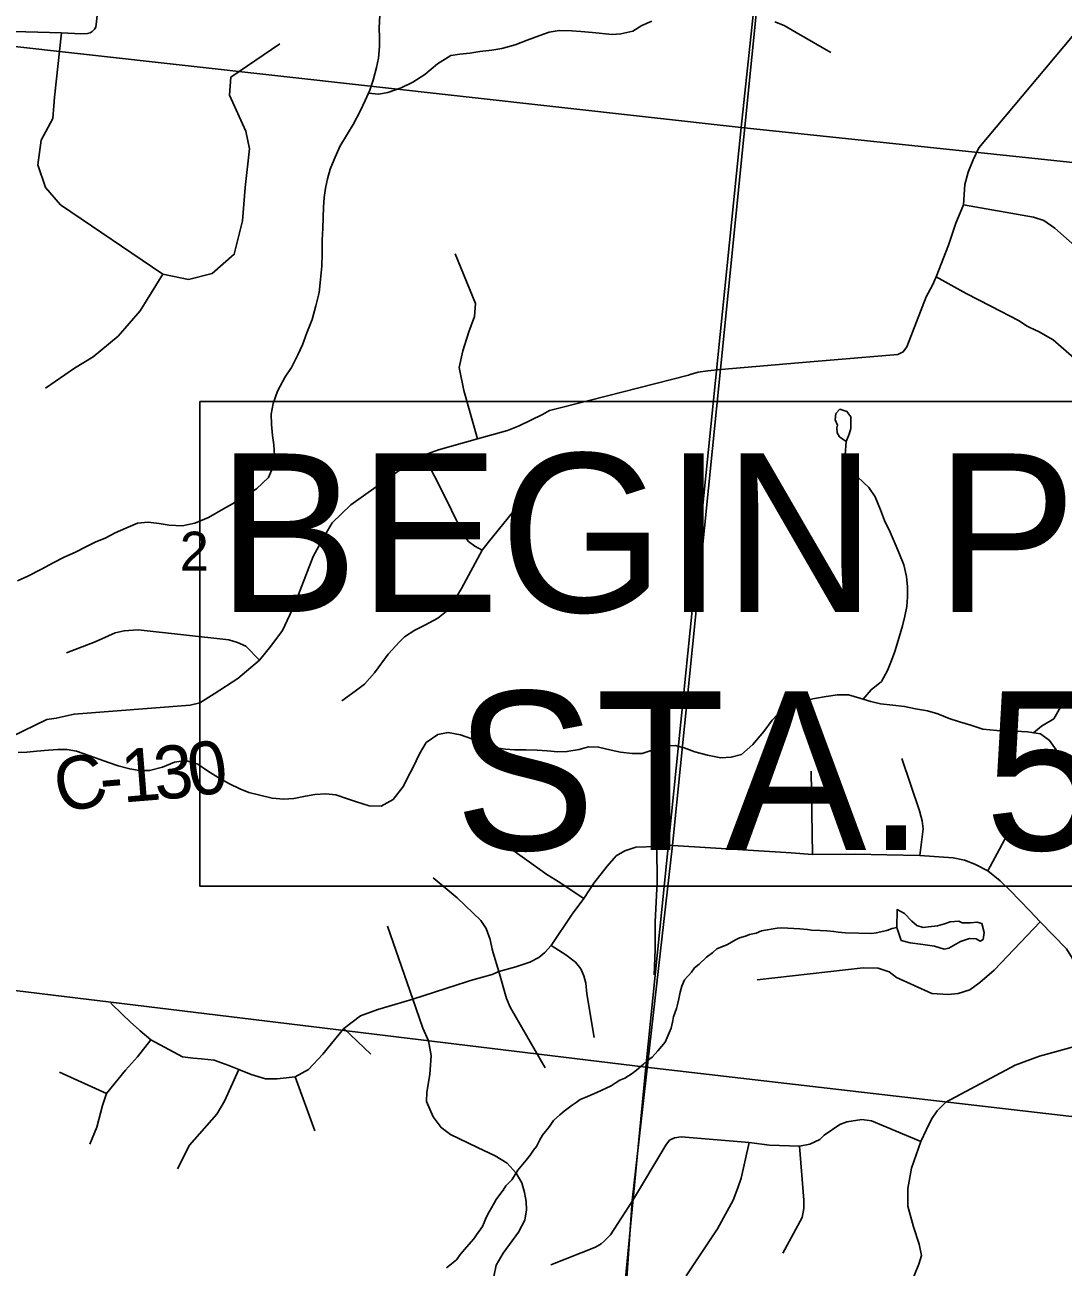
# Model space of a CAD drawing. Extents: x 0 to 43.4, y -8.1 to 22.
# Drawn here: x 3.172 to 4.286, y 18.481 to 19.813 of the extents above; entities that cross this region are included whole.
import ezdxf

# ---------------------------------------------------------------- set-up
doc = ezdxf.new("R2010")
doc.units = 0
for name, color, linetype in [('GM_X_Corporation', 7, 'Continuous'), ('GM_X_County_Road', 7, 'Continuous'), ('GM_X_County_Road_Text', 7, 'Continuous'), ('GM_X_Minor_Lake', 7, 'Continuous'), ('GM_X_Minor_River', 7, 'Continuous'), ('GM_X_Section_Text', 7, 'Continuous'), ('GM_X_Township_Road', 7, 'Continuous'), ('SH_Masking', 7, 'Continuous'), ('SH_Text', 7, 'Continuous')]:
    doc.layers.add(name, color=color, linetype=linetype)

msp = doc.modelspace()

# ---------------------------------------------------------------- linework, layer by layer
at = {"layer": 'GM_X_Corporation'}
for points in [[(8.9, 20.9), (4.0645, 20.9), (4.0111, 20.3696), (4.0006, 20.2658), (3.9936, 20.1953), (3.918, 19.4441), (3.8667, 18.9338), (3.8234, 18.5529), (3.8126, 18.3973), (3.8023, 18.3182), (3.7454, 17.7286), (3.744, 17.7149), (3.7921, 17.7096), (3.9407, 17.6938), (4.0716, 17.683), (4.1644, 17.6753), (4.3821, 17.6581)], [(3.8126, 18.3973), (3.8234, 18.5529), (3.8667, 18.9338), (3.918, 19.4441), (3.9936, 20.1953)]]:
    msp.add_lwpolyline(points, dxfattribs=at)
for points in [[(4.0476, 20.7082), (3.9403, 19.703), (2.9428, 19.8144), (3.042, 20.8098)], [(4.0476, 20.7082), (5.0456, 20.604), (4.9462, 19.5972), (3.9403, 19.703)], [(2.9428, 19.8144), (3.9403, 19.703), (3.8378, 18.6959), (2.8429, 18.8166)], [(3.9403, 19.703), (4.9462, 19.5972), (4.8473, 18.579), (3.8378, 18.6959)], [(3.8378, 18.6959), (3.7435, 17.7155), (2.8521, 17.7909), (2.8154, 17.7918), (2.8147, 17.7929), (2.7902, 17.8357), (2.7645, 17.8808), (2.7638, 17.882), (2.7489, 17.9091), (2.8429, 18.8166)], [(4.8473, 18.579), (4.7377, 17.6242), (3.7435, 17.7155), (3.8378, 18.6959)]]:
    msp.add_lwpolyline(points, close=True, dxfattribs=at)
at = {"layer": 'GM_X_County_Road'}
for points in [[(2.8955, 19.8202), (2.9503, 19.8114), (3.0205, 19.8099), (3.2114, 19.8047), (3.2321, 19.8036), (3.239, 19.8038), (3.2419, 19.8047), (3.244, 19.8059), (3.2466, 19.8085), (3.2479, 19.8108), (3.2621, 19.9316)], [(4.0143, 19.4518), (4.0184, 19.4522), (4.1083, 19.4599), (4.1141, 19.4627), (4.118, 19.468), (4.1385, 19.5218), (4.1456, 19.5341), (4.1492, 19.543), (4.1627, 19.577), (4.1706, 19.6007), (4.1786, 19.6202), (4.1801, 19.6419), (4.1838, 19.6551), (4.1891, 19.6686), (4.1952, 19.6814), (4.3047, 19.812)], [(3.8856, 19.4382), (3.8941, 19.4408), (3.9044, 19.4424), (3.9183, 19.4436), (4.0143, 19.4518)], [(3.1185, 19.0315), (3.1954, 19.0686), (3.2057, 19.0698), (3.2248, 19.0743), (3.3492, 19.0839), (3.3595, 19.0863), (3.375, 19.0962), (3.4005, 19.1126), (3.4235, 19.1322), (3.4356, 19.147), (3.4482, 19.1638), (3.4611, 19.1915), (3.4811, 19.2431), (3.4915, 19.2622), (3.5014, 19.2794), (3.5217, 19.2986), (3.5871, 19.3451), (3.5998, 19.352), (3.6155, 19.3577), (3.6575, 19.3695), (3.6897, 19.3785), (3.702, 19.3835), (3.727, 19.3954), (3.7347, 19.3998), (3.7772, 19.4106), (3.8838, 19.4376), (3.8856, 19.4382)], [(4.0436, 18.2811), (4.0476, 18.2871), (4.0548, 18.2983), (4.0665, 18.3252), (4.0876, 18.3787), (4.1308, 18.4847), (4.1337, 18.4941), (4.1313, 18.506), (4.125, 18.5247), (4.1188, 18.5469), (4.1189, 18.5659), (4.1229, 18.5875), (4.133, 18.6161), (4.1389, 18.6289), (4.1445, 18.6401), (4.1504, 18.6491), (4.1598, 18.6583), (4.2341, 18.6979), (4.2601, 18.7077), (4.3134, 18.7223)]]:
    msp.add_lwpolyline(points, dxfattribs=at)
at = {"layer": 'GM_X_Minor_Lake'}
for points in [[(4.0527, 19.3666), (4.056, 19.3743), (4.0577, 19.3804), (4.058, 19.3929), (4.0536, 19.3987), (4.0461, 19.4012), (4.0418, 19.3964), (4.0412, 19.3899), (4.0434, 19.3842)], [(4.0434, 19.3842), (4.0429, 19.3812), (4.0432, 19.3758), (4.0457, 19.3716), (4.0528, 19.3667)], [(4.112, 18.8316), (4.1214, 18.8291), (4.1327, 18.8277), (4.1475, 18.8254), (4.1581, 18.8225), (4.163, 18.8235), (4.1754, 18.8307), (4.185, 18.8339), (4.1922, 18.8333), (4.1967, 18.8309), (4.1997, 18.8328), (4.2007, 18.8403), (4.1983, 18.8499), (4.193, 18.8512), (4.1862, 18.8506), (4.1774, 18.8505), (4.1737, 18.8525), (4.1645, 18.8516), (4.1584, 18.8494), (4.1507, 18.8474), (4.1412, 18.8461), (4.1355, 18.8455), (4.1287, 18.8476), (4.1231, 18.8523), (4.1154, 18.8604), (4.1075, 18.8648), (4.1073, 18.8454)], [(4.1073, 18.8454), (4.1075, 18.8648), (4.1154, 18.8604), (4.1231, 18.8523), (4.1287, 18.8476), (4.1355, 18.8455), (4.1412, 18.8461), (4.1507, 18.8474), (4.1584, 18.8494), (4.1645, 18.8516), (4.1737, 18.8525), (4.1774, 18.8505), (4.1862, 18.8506), (4.193, 18.8512), (4.1983, 18.8499), (4.2007, 18.8403), (4.1997, 18.8328), (4.1967, 18.8309), (4.1922, 18.8333), (4.185, 18.8339), (4.1754, 18.8307), (4.163, 18.8235), (4.1581, 18.8225), (4.1475, 18.8254), (4.1327, 18.8277), (4.1214, 18.8291), (4.1119, 18.8317)], [(4.1073, 18.8454), (4.112, 18.8316)]]:
    msp.add_lwpolyline(points, dxfattribs=at)
at = {"layer": 'GM_X_Minor_River'}
for points in [[(3.3043, 19.28), (3.3161, 19.2785), (3.3267, 19.277), (3.3407, 19.2763), (3.3544, 19.2789), (3.369, 19.285), (3.3849, 19.2944), (3.3945, 19.2998), (3.4081, 19.3082), (3.4204, 19.3158), (3.4333, 19.328), (3.4374, 19.3378), (3.4397, 19.3514), (3.4389, 19.3628), (3.4377, 19.3731), (3.4365, 19.3846), (3.4361, 19.396), (3.4383, 19.4073), (3.4428, 19.4205), (3.4513, 19.4358), (3.458, 19.4459), (3.4649, 19.4594), (3.4697, 19.4703), (3.4743, 19.4831), (3.48, 19.4974), (3.4842, 19.5121), (3.4877, 19.5264), (3.4892, 19.5401), (3.4904, 19.5545), (3.4908, 19.5682), (3.4908, 19.5822), (3.4916, 19.5951), (3.4922, 19.6179), (3.4929, 19.6282), (3.4943, 19.638), (3.4965, 19.6482), (3.4995, 19.6584), (3.5036, 19.6689), (3.5097, 19.6828), (3.518, 19.6963), (3.524, 19.7064), (3.5316, 19.7206), (3.5369, 19.7322), (3.5418, 19.7431), (3.5455, 19.754), (3.549, 19.7676), (3.5511, 19.7774), (3.5523, 19.7899), (3.5522, 19.7998), (3.5521, 19.8101), (3.5525, 19.8234)], [(3.5403, 19.7399), (3.5515, 19.739), (3.5611, 19.7407), (3.5757, 19.7456), (3.588, 19.7517), (3.6011, 19.76), (3.6144, 19.7715), (3.6287, 19.7802), (3.6386, 19.7818), (3.6493, 19.783), (3.66, 19.7846), (3.6729, 19.7861), (3.6836, 19.7877), (3.6978, 19.7919), (3.7108, 19.7968), (3.7243, 19.8018), (3.7342, 19.8053), (3.7449, 19.8073), (3.7586, 19.8069), (3.7684, 19.8062), (3.7806, 19.8051), (3.8018, 19.803), (3.8113, 19.8035), (3.8239, 19.8065), (3.8336, 19.8124), (3.8443, 19.817)], [(3.9765, 19.8166), (3.9862, 19.8126), (3.9993, 19.805), (4.0363, 19.7834)], [(4.0712, 19.0903), (4.0796, 19.1005), (4.0909, 19.1093), (4.0973, 19.1209), (4.1014, 19.1318), (4.1051, 19.1416), (4.1097, 19.1567), (4.1131, 19.1691), (4.1157, 19.1793), (4.1179, 19.1895), (4.1185, 19.1998), (4.1185, 19.2108), (4.1177, 19.2218), (4.1146, 19.2345), (4.1093, 19.2475), (4.1043, 19.2595), (4.1001, 19.2695), (4.094, 19.2818), (4.0897, 19.2933), (4.0841, 19.3072), (4.0771, 19.3173), (4.0653, 19.3283), (4.0555, 19.3426), (4.0519, 19.3522), (4.0527, 19.3666)], [(3.1639, 19.2171), (3.1751, 19.2221), (3.1897, 19.2296), (3.2024, 19.2365), (3.214, 19.2426), (3.2263, 19.248), (3.2379, 19.2541), (3.2475, 19.2588), (3.2587, 19.2634), (3.2687, 19.2688), (3.2802, 19.2738), (3.2929, 19.2791), (3.3043, 19.28)], [(3.1647, 19.033), (3.1742, 19.0335), (3.1848, 19.0347), (3.1974, 19.0355), (3.2073, 19.0364), (3.2172, 19.0365), (3.2274, 19.0346), (3.2405, 19.0301), (3.2518, 19.026), (3.2616, 19.0226), (3.2721, 19.0189), (3.2845, 19.0155), (3.2944, 19.0137), (3.3058, 19.0138), (3.3195, 19.0176), (3.3326, 19.0229), (3.3444, 19.0245), (3.3576, 19.0207), (3.3677, 19.0135), (3.3792, 19.0064), (3.3916, 18.9996), (3.4024, 18.9943), (3.4122, 18.9902), (3.4227, 18.9876), (3.4371, 18.9842), (3.4496, 18.9831), (3.4606, 18.9839), (3.4728, 18.9862), (3.4831, 18.9882), (3.4949, 18.989), (3.5055, 18.9879), (3.5179, 18.9834), (3.5277, 18.9801), (3.5413, 18.9759), (3.5542, 18.9755), (3.5669, 18.9828), (3.578, 18.9969), (3.5828, 19.0067), (3.588, 19.0168), (3.5953, 19.0318), (3.6025, 19.0437), (3.6149, 19.0525), (3.6259, 19.0545), (3.6392, 19.0522), (3.6501, 19.0481), (3.661, 19.0436), (3.6745, 19.0386), (3.6873, 19.0368), (3.6972, 19.0361), (3.7094, 19.0361), (3.7215, 19.0358), (3.7321, 19.0351), (3.7435, 19.034), (3.7533, 19.0341), (3.7663, 19.0364), (3.7763, 19.0392), (3.7873, 19.0389), (3.8009, 19.0358), (3.8107, 19.0336), (3.8232, 19.0321), (3.8342, 19.0322), (3.8468, 19.0364), (3.8564, 19.0403), (3.8694, 19.0407), (3.8792, 19.0381), (3.8904, 19.034), (3.904, 19.0302), (3.9184, 19.0275), (3.9294, 19.028), (3.9405, 19.0311), (3.9529, 19.0417), (3.9647, 19.0555), (3.9735, 19.0678), (3.984, 19.0789), (3.9941, 19.0847), (4.0037, 19.0878), (4.0189, 19.0912), (4.0315, 19.0931), (4.0437, 19.0951), (4.0555, 19.0951), (4.0676, 19.0913), (4.0792, 19.088), (4.0898, 19.0854), (4.103, 19.0839), (4.1155, 19.0824), (4.1272, 19.0801), (4.1401, 19.0779), (4.151, 19.0745), (4.1634, 19.0696)], [(4.2539, 19.0543), (4.2623, 19.0615), (4.2754, 19.0691), (4.2826, 19.0818), (4.2887, 19.0957)], [(4.1634, 19.0696), (4.1743, 19.0662), (4.1867, 19.0625), (4.1995, 19.0583), (4.2143, 19.0567), (4.2245, 19.0561), (4.2344, 19.0562), (4.2473, 19.0554), (4.2613, 19.0531), (4.271, 19.046), (4.2797, 19.0336), (4.2881, 19.0212)], [(3.6243, 18.4808), (3.6349, 18.4892), (3.6393, 18.4955), (3.6456, 18.5028), (3.6535, 18.5117), (3.6563, 18.5162), (3.6627, 18.5251), (3.6647, 18.5292), (3.6668, 18.5348), (3.6701, 18.5408), (3.6725, 18.5449), (3.6774, 18.5538), (3.6813, 18.5594), (3.6849, 18.5638), (3.6877, 18.5687), (3.6944, 18.5749), (3.6968, 18.579), (3.7008, 18.5853), (3.7096, 18.596), (3.7139, 18.6016), (3.7175, 18.6068), (3.7207, 18.6109), (3.7244, 18.618), (3.7272, 18.6228), (3.7347, 18.6324), (3.7388, 18.6388), (3.7458, 18.6446), (3.7505, 18.6486), (3.7591, 18.6552), (3.7633, 18.6581), (3.7676, 18.6613), (3.773, 18.6634), (3.7853, 18.6687), (3.8008, 18.6758), (3.805, 18.6787), (3.8101, 18.6819), (3.8155, 18.684), (3.8233, 18.6891), (3.8279, 18.6927), (3.8354, 18.6989), (3.8397, 18.7029), (3.8447, 18.7066), (3.851, 18.7132), (3.8586, 18.7228), (3.8607, 18.7277), (3.8652, 18.7378), (3.8665, 18.7442), (3.8675, 18.7499), (3.8708, 18.7589), (3.8722, 18.7645), (3.8735, 18.769), (3.8749, 18.7762), (3.8766, 18.7826), (3.8795, 18.7894), (3.887, 18.7978), (3.8902, 18.8023), (3.8953, 18.8063), (3.9031, 18.8136), (3.9097, 18.8187), (3.914, 18.8228), (3.9256, 18.8273), (3.9341, 18.8323), (3.9384, 18.8345), (3.9449, 18.8361), (3.9491, 18.8379), (3.9564, 18.8395), (3.9622, 18.842), (3.979, 18.8448), (3.9839, 18.8451), (4.0032, 18.844), (4.0112, 18.8434), (4.0157, 18.8428), (4.0248, 18.8425), (4.032, 18.8419), (4.0396, 18.8412), (4.0441, 18.8407), (4.0521, 18.84), (4.0805, 18.8391), (4.0851, 18.8397), (4.0966, 18.8423), (4.1023, 18.8444), (4.1073, 18.8454)]]:
    msp.add_lwpolyline(points, dxfattribs=at)
at = {"layer": 'GM_X_Township_Road'}
for p, q in [((4.0167, 18.9238), (4.0153, 19.0132)), ((4.2047, 18.9062), (4.2328, 18.9581)), ((3.5432, 18.7098), (3.5142, 18.7374)), ((3.2092, 18.6906), (3.2594, 18.6675)), ((3.4828, 18.6276), (3.462, 18.6856))]:
    msp.add_line(p, q, dxfattribs=at)
for points in [[(3.2114, 19.8047), (3.2038, 19.7357), (3.2018, 19.7129), (3.1894, 19.6894), (3.1859, 19.6632), (3.1942, 19.639), (3.2101, 19.6204), (3.3198, 19.5458)], [(3.3198, 19.5458), (3.3474, 19.5403), (3.373, 19.5465), (3.3965, 19.5672), (3.4054, 19.6031), (3.4082, 19.639), (3.413, 19.6804), (3.4089, 19.6991), (3.3916, 19.7377), (3.393, 19.7571), (3.4455, 19.793)], [(4.1786, 19.6202), (4.2536, 19.6069), (4.2648, 19.6034), (4.2768, 19.5954), (4.3014, 19.5735), (4.3061, 19.5697)], [(3.6575, 19.3695), (3.6427, 19.4213), (3.6379, 19.4459), (3.6418, 19.4638), (3.648, 19.484), (3.6543, 19.5004), (3.6553, 19.5144), (3.6336, 19.5679)], [(3.1942, 19.4236), (3.2253, 19.445), (3.2453, 19.4574), (3.2722, 19.4795), (3.2957, 19.5065), (3.3198, 19.5458)], [(4.1492, 19.543), (4.1816, 19.5253), (4.2081, 19.5118), (4.2384, 19.496), (4.2464, 19.4904), (4.2507, 19.4885)], [(4.2507, 19.4885), (4.2592, 19.4845), (4.2748, 19.4754), (4.2974, 19.4558)], [(3.6626, 19.2501), (3.6546, 19.2545), (3.6478, 19.2594), (3.6426, 19.2658), (3.6232, 19.3061), (3.5998, 19.352)], [(3.5119, 19.0887), (3.5263, 19.0989), (3.5362, 19.1065), (3.5469, 19.1185), (3.5617, 19.1385), (3.5737, 19.1517), (3.5792, 19.157), (3.5903, 19.1644), (3.6011, 19.1696), (3.6149, 19.1773), (3.6257, 19.1856), (3.6303, 19.1923), (3.6401, 19.2089), (3.6626, 19.2501), (3.669, 19.2584), (3.701, 19.2978)], [(3.2166, 19.1399), (3.2474, 19.1519), (3.2687, 19.1616), (3.2784, 19.1637), (3.2936, 19.1647), (3.3906, 19.154), (3.3999, 19.1509), (3.4089, 19.1471), (3.4235, 19.1322)], [(4.1318, 18.9227), (4.1355, 18.9515), (4.1342, 18.9599), (4.1315, 18.9706), (4.1125, 19.0266)], [(3.741, 18.8967), (3.7318, 18.9025), (3.6599, 18.9538)], [(3.8602, 18.9337), (3.8499, 18.9324), (3.8273, 18.9317), (3.8156, 18.9279), (3.8063, 18.9224), (3.7966, 18.9114), (3.7821, 18.8931), (3.7714, 18.8765)], [(3.847, 18.7947), (3.848, 18.822), (3.8481, 18.8516), (3.8501, 18.8941), (3.8499, 18.9324)], [(4.3134, 18.7223), (4.3026, 18.7633), (4.3023, 18.7805), (4.2994, 18.7972), (4.2957, 18.8125), (4.2893, 18.8227), (4.2609, 18.8518), (4.2493, 18.8637), (4.2287, 18.8852), (4.218, 18.8956), (4.2047, 18.9062), (4.191, 18.9135), (4.1798, 18.9178), (4.1675, 18.9202), (4.1318, 18.9227), (4.0964, 18.9235), (4.0624, 18.9241), (4.0167, 18.9238), (3.994, 18.9256), (3.8669, 18.9333), (3.8602, 18.9337)], [(3.6743, 18.8183), (3.6731, 18.8223), (3.6711, 18.8327), (3.6667, 18.8444), (3.6609, 18.853), (3.6355, 18.8775), (3.6099, 18.8989)], [(3.7714, 18.8765), (3.744, 18.8948), (3.741, 18.8967)], [(3.7714, 18.8765), (3.7589, 18.8598), (3.7366, 18.8261), (3.7296, 18.8188), (3.7232, 18.8133), (3.7135, 18.8083), (3.6985, 18.8035), (3.6802, 18.7983), (3.6731, 18.795), (3.6525, 18.7895), (3.6466, 18.7876)], [(3.6748, 18.4716), (3.6774, 18.4835), (3.6848, 18.4963), (3.7015, 18.5191), (3.7081, 18.5317), (3.71, 18.5429), (3.7095, 18.5519), (3.7079, 18.5615), (3.7048, 18.5719), (3.6988, 18.5822), (3.6894, 18.5929), (3.6765, 18.6009), (3.6575, 18.6098), (3.6283, 18.6238), (3.6183, 18.6311), (3.6097, 18.6426), (3.6026, 18.6589), (3.6032, 18.6692), (3.6064, 18.688), (3.6078, 18.7084), (3.6047, 18.7239), (3.5987, 18.7377), (3.588, 18.7686), (3.561, 18.8469)], [(3.9575, 18.7893), (4.0711, 18.8024), (4.087, 18.802), (4.0988, 18.7982), (4.1069, 18.7919), (4.1448, 18.7747), (4.1623, 18.7738), (4.1731, 18.7747), (4.1855, 18.7789), (4.1963, 18.7866), (4.2115, 18.7998), (4.2609, 18.8518)], [(3.73, 18.6951), (3.6926, 18.7603), (3.6887, 18.7695), (3.6802, 18.7983), (3.6743, 18.8183)], [(3.7825, 18.7277), (3.7748, 18.7743), (3.7735, 18.7858), (3.7716, 18.7937), (3.7681, 18.8014), (3.7627, 18.8083), (3.7523, 18.8163), (3.7366, 18.8261)], [(3.6466, 18.7876), (3.588, 18.7686), (3.5688, 18.763)], [(3.2946, 18.7359), (3.2851, 18.7441), (3.2765, 18.7524), (3.2641, 18.7645)], [(3.5688, 18.763), (3.5505, 18.7577), (3.5321, 18.7508), (3.5142, 18.7374), (3.5042, 18.7253), (3.4914, 18.7099), (3.4762, 18.6932), (3.462, 18.6856), (3.4426, 18.6834), (3.4299, 18.6833), (3.4148, 18.688), (3.4016, 18.6932), (3.3924, 18.6969)], [(3.2416, 18.6133), (3.2492, 18.6316), (3.2553, 18.6547), (3.2594, 18.6675), (3.28, 18.6925), (3.2926, 18.707), (3.3069, 18.7251)], [(3.3924, 18.6969), (3.3906, 18.6977), (3.3751, 18.7032), (3.3614, 18.7046), (3.3523, 18.7056), (3.3412, 18.707), (3.3069, 18.7251), (3.2958, 18.7348), (3.2946, 18.7359)], [(3.3357, 18.5869), (3.3485, 18.6123), (3.3778, 18.6455), (3.3859, 18.6595), (3.4016, 18.6932)], [(4.133, 18.6161), (4.08, 18.6382), (4.0695, 18.6398), (4.0537, 18.6372), (4.046, 18.6342), (4.0293, 18.6231), (4.0247, 18.6184), (4.0139, 18.6134), (4.0029, 18.6113), (3.9706, 18.6122), (3.9488, 18.6152), (3.8759, 18.621), (3.8686, 18.6202), (3.8635, 18.6177), (3.8594, 18.6123), (3.8236, 18.5524)], [(3.8814, 18.4722), (3.9147, 18.5227), (3.9318, 18.5534), (3.9368, 18.5665), (3.9401, 18.5767), (3.9488, 18.6152)], [(4.0029, 18.6113), (4.0074, 18.5532), (4.0076, 18.5444), (4.0056, 18.5347), (3.9848, 18.4963)], [(3.8236, 18.5524), (3.7999, 18.5162), (3.7936, 18.5096), (3.7902, 18.5065), (3.784, 18.5029), (3.736, 18.484)]]:
    msp.add_lwpolyline(points, dxfattribs=at)
at = {"layer": 'SH_Masking'}
msp.add_lwpolyline([(3.3595, 19.4094), (5.117, 19.4094), (5.117, 18.89), (3.3595, 18.89)], close=True, dxfattribs=at)
at = {"layer": 'SH_Text'}
msp.add_lwpolyline([(3.3595, 19.4094), (5.117, 19.4094), (5.117, 18.89), (3.3595, 18.89)], close=True, dxfattribs=at)

# ---------------------------------------------------------------- texts
at = {"layer": 'GM_X_County_Road_Text'}
for s, rotation, p in [('0', 7.8471, (3.3504, 18.9856)), ('C', 13.7049, (3.211, 18.9669)), ('1', 4.6157, (3.2772, 18.9795)), ('3', 4.8011, (3.3123, 18.9823)), ('-', 4.7593, (3.254, 18.9775))]:
    msp.add_text(s, height=0.0568, rotation=rotation, dxfattribs=at).set_placement(p)
at = {"layer": 'GM_X_Section_Text'}
msp.add_text('2', height=0.0419, rotation=0, dxfattribs=at).set_placement((3.3381, 19.228))
at = {"layer": 'SH_Text'}
for s, p in [('BEGIN PROJECT', (3.3778, 19.1837)), ('STA. 53+00', (3.6326, 18.9287))]:
    msp.add_text(s, height=0.17, dxfattribs=at).set_placement(p)

doc.saveas('drawing.dxf')
